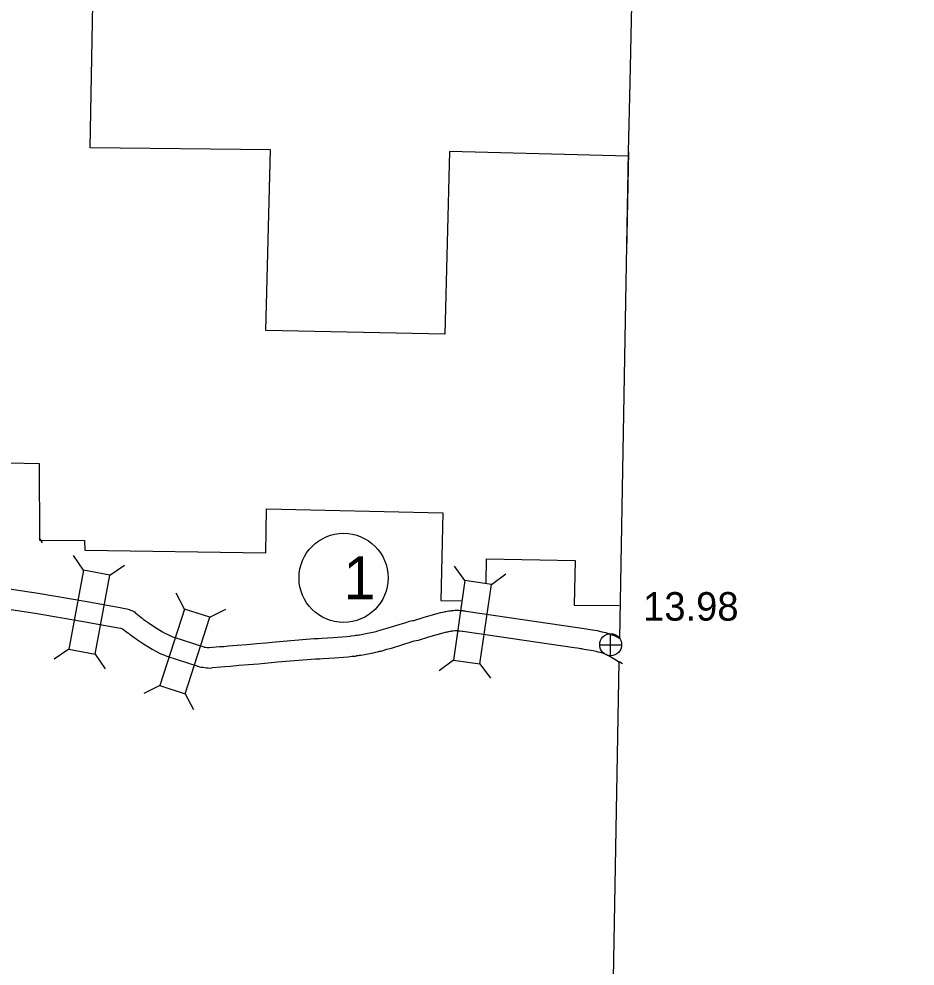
# Model space of a CAD drawing. Extents: x -939622 to -934245, y 1383184 to 1385301.
# Drawn here: x -936292.55 to -936252.72, y 1384456.03 to 1384498.09 of the extents above; entities that cross this region are included whole.
import ezdxf

# ---------------------------------------------------------------- set-up
doc = ezdxf.new("R2010")
doc.units = 0
for name, color, linetype in [('Level 10', 7, 'Continuous'), ('Level 2', 7, 'Continuous'), ('Level 20', 7, 'Continuous'), ('Level 25', 7, 'Continuous'), ('Level 26', 7, 'Continuous'), ('Level 27', 7, 'Continuous'), ('Level 7', 7, 'Continuous')]:
    doc.layers.add(name, color=color, linetype=linetype)

msp = doc.modelspace()

# ---------------------------------------------------------------- linework, layer by layer
at = {"layer": 'Level 10'}
for points in [[(-936297.595, 1384473.481), (-936291.687, 1384472.599), (-936289.601, 1384472.239), (-936288.05, 1384471.951), (-936287.842, 1384471.914), (-936287.752, 1384471.893), (-936287.644, 1384471.87), (-936287.584, 1384471.844), (-936287.524, 1384471.825), (-936287.417, 1384471.756), (-936287.376, 1384471.717), (-936287.354, 1384471.697), (-936287.21, 1384471.584), (-936287.133, 1384471.528), (-936287.073, 1384471.48), (-936287.01, 1384471.429), (-936286.932, 1384471.376), (-936286.842, 1384471.321), (-936286.754, 1384471.255), (-936286.517, 1384471.1), (-936286.168, 1384470.876), (-936286.056, 1384470.815), (-936285.93, 1384470.757), (-936285.864, 1384470.722), (-936285.804, 1384470.698), (-936285.718, 1384470.66), (-936285.661, 1384470.635), (-936284.327, 1384470.205), (-936284.31, 1384470.2), (-936284.301, 1384470.198), (-936284.256, 1384470.192), (-936284.18, 1384470.182), (-936284.168, 1384470.181), (-936284.14, 1384470.181), (-936284.097, 1384470.179), (-936283.627, 1384470.223), (-936283.445, 1384470.229), (-936283.235, 1384470.247), (-936282.854, 1384470.29), (-936282.414, 1384470.317), (-936281.972, 1384470.354), (-936281.567, 1384470.391), (-936281.143, 1384470.435), (-936279.424, 1384470.575), (-936279.231, 1384470.581), (-936279.083, 1384470.593), (-936278.586, 1384470.62), (-936278.196, 1384470.653), (-936277.995, 1384470.669), (-936277.834, 1384470.687), (-936277.775, 1384470.691), (-936277.636, 1384470.714), (-936277.574, 1384470.723), (-936277.498, 1384470.732), (-936277.435, 1384470.736), (-936277.411, 1384470.739), (-936277.058, 1384470.809)], [(-936297.725, 1384472.591), (-936291.83, 1384471.71), (-936289.76, 1384471.353), (-936288.212, 1384471.066), (-936288.023, 1384471.032), (-936287.945, 1384471.014), (-936287.94, 1384471.013), (-936287.754, 1384470.867), (-936287.68, 1384470.813), (-936287.637, 1384470.778), (-936287.548, 1384470.706), (-936287.42, 1384470.619), (-936287.347, 1384470.574), (-936287.271, 1384470.517), (-936287.005, 1384470.345), (-936286.627, 1384470.101), (-936286.462, 1384470.011), (-936286.328, 1384469.949), (-936286.237, 1384469.902), (-936286.152, 1384469.868), (-936286.081, 1384469.837), (-936285.981, 1384469.793), (-936284.6, 1384469.348), (-936284.526, 1384469.324), (-936284.444, 1384469.31), (-936284.376, 1384469.3), (-936284.29, 1384469.289), (-936284.212, 1384469.28), (-936284.156, 1384469.281), (-936284.144, 1384469.28), (-936284.016, 1384469.265), (-936283.941, 1384469.29), (-936283.569, 1384469.325), (-936283.392, 1384469.331), (-936283.147, 1384469.351), (-936282.776, 1384469.393), (-936282.349, 1384469.419), (-936281.893, 1384469.458), (-936281.48, 1384469.495), (-936281.06, 1384469.539), (-936279.372, 1384469.676), (-936279.181, 1384469.683), (-936279.024, 1384469.695), (-936278.523, 1384469.722), (-936278.123, 1384469.756), (-936277.912, 1384469.772), (-936277.751, 1384469.79), (-936277.708, 1384469.793), (-936277.589, 1384469.801), (-936277.524, 1384469.821), (-936277.5, 1384469.825), (-936277.461, 1384469.83), (-936277.417, 1384469.835), (-936277.349, 1384469.839), (-936277.265, 1384469.85), (-936276.884, 1384469.926)], [(-936277.053, 1384470.81), (-936276.971, 1384470.825), (-936276.902, 1384470.84), (-936276.813, 1384470.866), (-936276.752, 1384470.879), (-936276.674, 1384470.895), (-936276.649, 1384470.899), (-936276.45, 1384470.963), (-936276.247, 1384471.019), (-936275.352, 1384471.294), (-936275.195, 1384471.35), (-936275.044, 1384471.373), (-936275.001, 1384471.38), (-936274.59, 1384471.51), (-936273.815, 1384471.732), (-936273.726, 1384471.753), (-936273.639, 1384471.77), (-936273.586, 1384471.777), (-936273.575, 1384471.779), (-936273.518, 1384471.793), (-936273.436, 1384471.803), (-936273.392, 1384471.808), (-936273.372, 1384471.81), (-936273.319, 1384471.819), (-936273.269, 1384471.82), (-936273.257, 1384471.822), (-936273.238, 1384471.824), (-936273.154, 1384471.838), (-936273.079, 1384471.831), (-936273.053, 1384471.83), (-936272.993, 1384471.831), (-936272.937, 1384471.822), (-936272.903, 1384471.819), (-936272.895, 1384471.818), (-936272.819, 1384471.819), (-936272.785, 1384471.809), (-936272.737, 1384471.805), (-936272.686, 1384471.797), (-936267.729, 1384471.073), (-936267.601, 1384471.05), (-936267.529, 1384471.039), (-936267.429, 1384471.029), (-936267.329, 1384471.002), (-936267.271, 1384470.989), (-936266.855, 1384470.927), (-936266.703, 1384470.89), (-936266.635, 1384470.875), (-936266.61, 1384470.871), (-936266.553, 1384470.867), (-936266.462, 1384470.841), (-936266.448, 1384470.836), (-936266.438, 1384470.833), (-936266.395, 1384470.823), (-936266.338, 1384470.8), (-936266.316, 1384470.79), (-936266.292, 1384470.781), (-936266.226, 1384470.755), (-936266.199, 1384470.745), (-936266.138, 1384470.723), (-936266.063, 1384470.691), (-936265.847, 1384470.578)], [(-936276.889, 1384469.925), (-936276.792, 1384469.943), (-936276.682, 1384469.967), (-936276.592, 1384469.993), (-936276.564, 1384469.999), (-936276.517, 1384470.009), (-936276.446, 1384470.019), (-936276.193, 1384470.101), (-936275.996, 1384470.154), (-936275.069, 1384470.44), (-936274.976, 1384470.473), (-936274.9, 1384470.484), (-936274.788, 1384470.504), (-936274.33, 1384470.648), (-936273.591, 1384470.86), (-936273.537, 1384470.873), (-936273.493, 1384470.882), (-936273.439, 1384470.889), (-936273.384, 1384470.9), (-936273.357, 1384470.906), (-936273.332, 1384470.909), (-936273.304, 1384470.912), (-936273.244, 1384470.918), (-936273.159, 1384470.927), (-936273.114, 1384470.932), (-936273.071, 1384470.93), (-936273.021, 1384470.926), (-936272.969, 1384470.917), (-936272.958, 1384470.917), (-936272.851, 1384470.911), (-936272.839, 1384470.91), (-936272.824, 1384470.908), (-936267.871, 1384470.184), (-936267.746, 1384470.162), (-936267.644, 1384470.146), (-936267.594, 1384470.141), (-936267.549, 1384470.129), (-936267.439, 1384470.104), (-936267.027, 1384470.042), (-936266.903, 1384470.012), (-936266.814, 1384469.993), (-936266.725, 1384469.976), (-936266.711, 1384469.975), (-936266.675, 1384469.964), (-936266.67, 1384469.963), (-936266.652, 1384469.955), (-936266.615, 1384469.941), (-936266.549, 1384469.915), (-936266.515, 1384469.903), (-936266.468, 1384469.885), (-936266.446, 1384469.876), (-936266.441, 1384469.873), (-936266.395, 1384469.846), (-936266.368, 1384469.833), (-936266.314, 1384469.8), (-936266.29, 1384469.791), (-936266.063, 1384469.656), (-936265.855, 1384469.531)], [(-936265.728, 1384469.455), (-936265.866, 1384469.541)]]:
    msp.add_lwpolyline(points, dxfattribs=at)
at = {"layer": 'Level 2'}
for points in [[(-936265.468, 1384491.995), (-936273.408, 1384492.204), (-936273.619, 1384484.093), (-936281.576, 1384484.253), (-936281.364, 1384492.277), (-936289.38, 1384492.364), (-936289.027, 1384511.532)], [(-936265.468, 1384491.995), (-936273.408, 1384492.204), (-936273.619, 1384484.093), (-936281.576, 1384484.253), (-936281.364, 1384492.277), (-936289.38, 1384492.364), (-936289.027, 1384511.532)], [(-936265.387, 1384495.268), (-936265.253, 1384501.484), (-936252.724, 1384501.444)], [(-936265.456, 1384492.197), (-936265.387, 1384495.268)], [(-936265.456, 1384492.197), (-936265.387, 1384495.268)], [(-936265.847, 1384470.578), (-936265.456, 1384492.197)], [(-936265.456, 1384492.197), (-936265.551, 1384487.752)], [(-936308.362, 1384452.998), (-936298.32, 1384452.764), (-936289.92, 1384452.615), (-936274.395, 1384452.342), (-936266.18, 1384452.177), (-936265.866, 1384469.541)]]:
    msp.add_lwpolyline(points, dxfattribs=at)
at = {"layer": 'Level 20'}
for p, q in [((-936289.677, 1384473.607), (-936290.126, 1384474.26)), ((-936288.509, 1384473.391), (-936287.857, 1384473.839)), ((-936272.724, 1384473.149), (-936273.197, 1384473.784)), ((-936271.548, 1384472.977), (-936270.913, 1384473.45)), ((-936285.193, 1384471.884), (-936285.554, 1384472.589)), ((-936284.062, 1384471.519), (-936283.357, 1384471.88)), ((-936290.327, 1384470.103), (-936290.98, 1384469.654)), ((-936289.159, 1384469.886), (-936288.71, 1384469.234)), ((-936273.239, 1384469.622), (-936273.874, 1384469.149)), ((-936272.064, 1384469.45), (-936271.591, 1384468.815)), ((-936286.286, 1384468.492), (-936286.991, 1384468.131)), ((-936285.156, 1384468.127), (-936284.795, 1384467.422))]:
    msp.add_line(p, q, dxfattribs=at)
for points in [[(-936289.159, 1384469.886), (-936288.509, 1384473.391), (-936289.677, 1384473.607), (-936290.327, 1384470.103)], [(-936272.064, 1384469.45), (-936271.548, 1384472.977), (-936272.724, 1384473.149), (-936273.239, 1384469.622)], [(-936285.156, 1384468.127), (-936284.062, 1384471.519), (-936285.193, 1384471.884), (-936286.286, 1384468.492)]]:
    msp.add_lwpolyline(points, close=True, dxfattribs=at)
at = {"layer": 'Level 26'}
for p, q in [((-936266.251, 1384469.815), (-936266.251, 1384470.79)), ((-936266.738, 1384470.302), (-936265.763, 1384470.302))]:
    msp.add_line(p, q, dxfattribs=at)
msp.add_circle((-936266.251, 1384470.302), 0.487, dxfattribs=at)
at = {"layer": 'Level 27'}
msp.add_ellipse((-936278.119, 1384473.271), major_axis=(0, 1.98), ratio=0.999998, dxfattribs=at)
at = {"layer": 'Level 7'}
for points in [[(-936308.539, 1384476.958), (-936308.21, 1384476.973), (-936308.039, 1384476.964), (-936305.727, 1384476.916), (-936305.76, 1384476.024), (-936303.768, 1384475.994), (-936303.747, 1384476.309), (-936301.701, 1384476.745), (-936301.602, 1384476.753), (-936295.708, 1384476.598), (-936295.638, 1384478.442), (-936291.643, 1384478.349), (-936291.634, 1384474.948), (-936289.628, 1384474.936), (-936289.623, 1384474.498), (-936281.571, 1384474.382), (-936281.542, 1384476.333), (-936273.702, 1384476.162), (-936273.795, 1384472.264), (-936272.88, 1384472.252)], [(-936291.493, 1384474.832), (-936291.636, 1384475.046)], [(-936271.786, 1384473.05), (-936271.774, 1384474.11), (-936267.821, 1384474.046), (-936267.873, 1384472.064), (-936265.879, 1384472.049)]]:
    msp.add_lwpolyline(points, dxfattribs=at)

# ---------------------------------------------------------------- texts
at = {"layer": 'Level 25'}
msp.add_text('13.98', height=1.2672, dxfattribs=at).set_placement((-936264.808, 1384471.371))
at = {"layer": 'Level 27'}
msp.add_text('1', height=1.901, dxfattribs=at).set_placement((-936278.119, 1384472.32))

doc.saveas('drawing.dxf')
